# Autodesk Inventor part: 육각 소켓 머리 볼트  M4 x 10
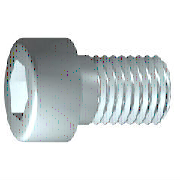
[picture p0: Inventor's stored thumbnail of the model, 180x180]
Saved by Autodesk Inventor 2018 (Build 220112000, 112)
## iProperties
Created: 2012-02
Part Number: 육각 소켓 머리 볼트  M4 x 10
Material: 스테인리스강
Description: 6각 소켓 머리 캡 나사
Document SubType Name: Modeling
Standard: ISO 4762
Designer: mdu-01
Standard Revision: Fourth edition 2004-03-01
Standards Organization: ISO
Language: ko-KR
Size Designation: M4 x 10
Categories: <MemberInstance><Categories><Category DisplayName="조임쇠" InternalName="e4da775c-781d-43d5-af7c-5136215cf5a6" Mnemonic="FSTN"><Category DisplayName="볼트" InternalN
Density: 7.75 g/cm^3
Appearance: 반광택
IsCustomPart: 1
Author: mdu-01
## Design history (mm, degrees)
sketch "스케치1"
  geometry: L1 (-1, 0)-(10, 0); L2 (10, 0)-(10, 2); L3 (10, 2)-(1.75, 2); L4 (1.75, 2)-(1.32, 2); L5 (1.32, 2)-(0, 2); L6 (0, 2)-(0, 3.5); L7 (0, 3.5)-(-4, 3.5); L8 (-4, 3.5)-(-4, 1.732); L9 (-4, 1.732)-(-2, 1.732); L10 (-2, 1.732)-(-1, 0); L11 (-6.8, 0)-(12.8, 0) reference; L12 (0, -0.7)-(0, 4.2) reference; L13 (1.75, 2)-(0, 2)
  constraints: 22 end point, 6 parallel, 2 collinear, 2 perpendicular, 1 horizontal, 1 point on line
  dimensions: "d1" = 8.25 distance from line of L3.end L2 (= GEL); "d2" = 0.42952 distance of L4.end L3.end (computed from GAL); "d3" = 4 distance between parallel lines of L8 L6 (= KOH); "d4" = 2 distance of L8.end L9.end (= INTI); "d5" = 60 deg angle of L10 L1; "d6" = 4 diameter of L3 L1 (= GD); "d7" = 4 diameter of L5 L1 (= BDM); "d8" = 3.4641 diameter of L9 L1 (= 1.1547 x SW); "d9" = 7 diameter of L7 L1 (= KOD); "d26" = 10 distance between parallel lines of L12 L2 (= NLG)
revolve "본체" sketch "스케치1" stored, may be unused: angle "d10" = 90 deg
sketch "스케치2"
  geometry: L1 (0, -4.9)-(0, 4.9) reference; L2 (-4.9, 0)-(4.9, 0) reference; L3 (1.732, 0)-(0.866, -1.5); L4 (0.866, -1.5)-(-0.866, -1.5); L5 (-0.866, -1.5)-(-1.732, 0); L6 (-1.732, 0)-(-0.866, 1.5); L7 (-0.866, 1.5)-(0.866, 1.5); L8 (0.866, 1.5)-(1.732, 0); 2 further points
  constraints: 12 end point, 1 coincident, 1 horizontal alignment, 1 point on line, 12 other
extrude "슬롯" join sketch "스케치2" stored distance "d11" = 10; taper "d12" = 0 deg
workplane "Work Plane1"
fillet "Fillet2" dims "d30" = 0.1 (= R)
body "Solid1"
fillet "모깎기1" dims "d17" = 0.4 (= RR)
feature "스레드" dims "d13" = 8.25 (= GEL), "d14" = 0
chamfer "모따기1" distance "d15" = 0.42941 (= -0.5 x SPD + 0.5 x GD); stored, may be unused: second distance "d16" = 0.42941 (= GUL), angle "d27" = 45 deg
other parameters: "GD" = 4 [user parameter; used in 2 equation terms], "NLG" = 10 [user parameter; used in 1 equation term], "GEL" = 8.25 [user parameter; used in 2 equation terms], "KOD" = 7 [user parameter; used in 1 equation term], "KOH" = 4 [user parameter; used in 1 equation term], "INTI" = 2 [user parameter; used in 1 equation term], "GAL" = 0.42941 (= 0.61345 x PTC) [user parameter; used in 1 equation term], "GUL" = 0.42941 (= 0.61345 x PTC) [user parameter; used in 1 equation term], "BDM" = 4 (= NND) [user parameter; used in 1 equation term], "SW" = 3 [user parameter; used in 2 equation terms], "RR" = 0.4 [user parameter; used in 1 equation term], "SPD" = 3.14117 (= NND - 1.2269 x PTC) [user parameter; used in 1 equation term], "d19" = 0, "d28" = 0, "d29" = 0, "R" = 0.1 [user parameter; used in 1 equation term], "TOA" = 30 deg [user parameter], "GD1" = 3.14117 (= THREADDIA - 1.2269 x PTC) [user parameter], "THREADDIA" = 4 [user parameter; used in 1 equation term], "FAWI" = 45 deg [user parameter], "TPU" = 14.28571 (computed from PTC) [user parameter], "PTC" = 0.7 [user parameter; used in 5 equation terms], "NND" = 4 [user parameter; used in 2 equation terms], "E0" = 3.465 (= 1.155 x SW) [user parameter]
